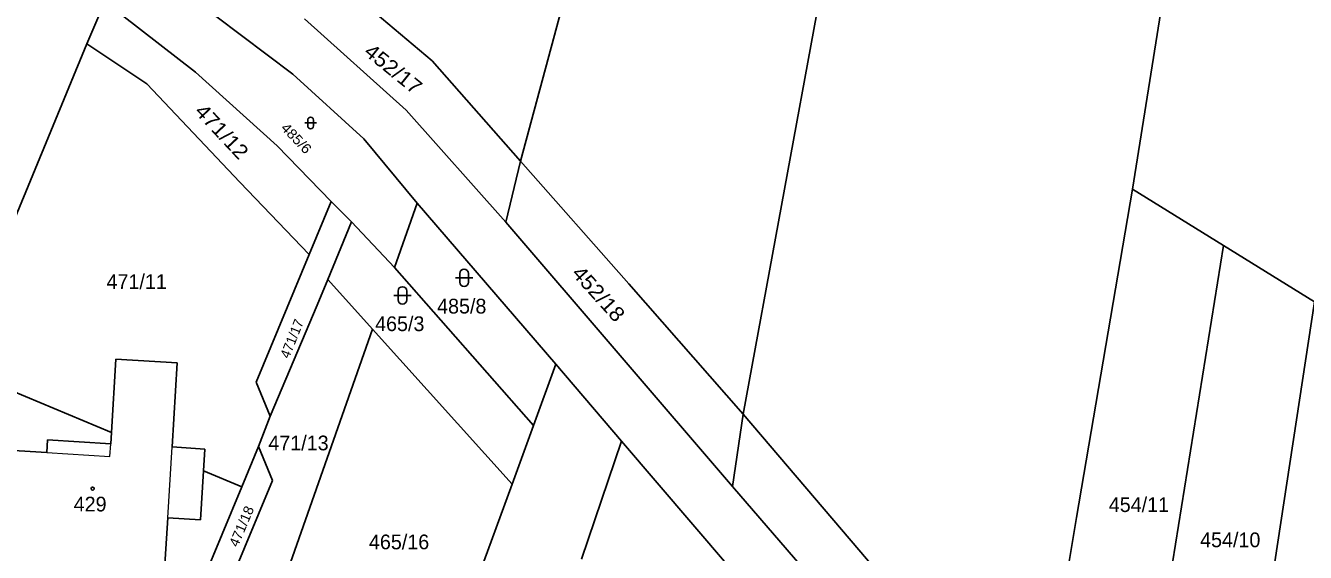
# Model space of a CAD drawing. Extents: x -701211 to -698780, y -1014269 to -1012378.
# Drawn here: x -699900.8 to -699753.2, y -1013426.5 to -1013365.7 of the extents above; entities that cross this region are included whole.
import ezdxf
from ezdxf.enums import TextEntityAlignment as Align

# ---------------------------------------------------------------- set-up
doc = ezdxf.new("R2010")
doc.units = 0
doc.header["$LTSCALE"] = 0.68
for name, color, linetype, lineweight in [('1', 7, 'Continuous', 25), ('3', 7, 'Continuous', 25), ('4', 7, 'Continuous', 13), ('5', 7, 'Continuous', 25)]:
    doc.layers.add(name, color=color, linetype=linetype, lineweight=lineweight)
doc.layers.add('2', color=7, linetype='Continuous')

msp = doc.modelspace()

# ---------------------------------------------------------------- linework, layer by layer
at = {"layer": '1'}
for p, q in [((-699773.11, -1013384.59), (-699763.06, -1013321.76)), ((-699829.74, -1013329.68), (-699843.69, -1013381.39)), ((-699806.32, -1013346.89), (-699818.01, -1013410.55)), ((-699869.94, -1013371.34), (-699889.02, -1013356.93)), ((-699853.88, -1013369.8), (-699867, -1013358.7)), ((-699893.69, -1013367.83), (-699891.63, -1013363.02)), ((-699891.63, -1013363.02), (-699881.16, -1013371.11)), ((-699856.87, -1013375.49), (-699868.6, -1013364.96)), ((-699909.05, -1013405.04), (-699893.69, -1013367.83)), ((-699893.69, -1013367.83), (-699886.78, -1013372.45)), ((-699843.69, -1013381.39), (-699853.88, -1013369.8)), ((-699881.16, -1013371.11), (-699871.73, -1013379.61)), ((-699861.76, -1013378.81), (-699869.94, -1013371.34)), ((-699886.78, -1013372.45), (-699876.06, -1013383.81)), ((-699845.37, -1013388.4), (-699856.87, -1013375.49)), ((-699871.73, -1013379.61), (-699865.53, -1013386.04)), ((-699855.6, -1013386.22), (-699861.76, -1013378.81)), ((-699845.37, -1013388.4), (-699843.69, -1013381.39)), ((-699831.2, -1013395.51), (-699843.69, -1013381.39)), ((-699876.06, -1013383.81), (-699868.05, -1013392.12)), ((-699779.57, -1013422.45), (-699773.11, -1013384.59)), ((-699773.11, -1013384.59), (-699762.6, -1013391.1)), ((-699865.53, -1013386.04), (-699868.05, -1013392.12)), ((-699863.17, -1013388.35), (-699865.53, -1013386.04)), ((-699858.22, -1013393.64), (-699855.6, -1013386.22)), ((-699839.59, -1013404.78), (-699855.6, -1013386.22)), ((-699865.9, -1013395.01), (-699863.17, -1013388.35)), ((-699858.22, -1013393.64), (-699863.17, -1013388.35)), ((-699819.25, -1013418.87), (-699845.37, -1013388.4)), ((-699762.6, -1013391.1), (-699773.55, -1013458.92)), ((-699762.6, -1013391.1), (-699752.13, -1013397.59)), ((-699868.05, -1013392.12), (-699874.17, -1013406.85)), ((-699842.18, -1013411.86), (-699858.22, -1013393.64)), ((-699867.13, -1013397.98), (-699865.9, -1013395.01)), ((-699860.73, -1013400.75), (-699865.9, -1013395.01)), ((-699818.01, -1013410.55), (-699831.2, -1013395.51)), ((-699867.13, -1013397.98), (-699872.55, -1013410.78)), ((-699762.78, -1013467.71), (-699752.13, -1013397.59)), ((-699872.65, -1013434.53), (-699860.73, -1013400.75)), ((-699844.65, -1013418.6), (-699860.73, -1013400.75)), ((-699890.85, -1013412.64), (-699890.33, -1013404.18)), ((-699890.33, -1013404.18), (-699883.26, -1013404.62)), ((-699883.26, -1013404.62), (-699883.86, -1013414.31)), ((-699839.59, -1013404.78), (-699842.18, -1013411.86)), ((-699832.02, -1013413.64), (-699839.59, -1013404.78)), ((-699909.05, -1013405.04), (-699890.85, -1013412.64)), ((-699874.17, -1013406.85), (-699872.55, -1013410.78)), ((-699819.25, -1013418.87), (-699818.01, -1013410.55)), ((-699784.21, -1013450.14), (-699818.01, -1013410.55)), ((-699873.9, -1013414.28), (-699872.55, -1013410.78)), ((-699844.65, -1013418.6), (-699842.18, -1013411.86)), ((-699898.23, -1013413.5), (-699898.32, -1013414.97)), ((-699890.93, -1013413.95), (-699898.23, -1013413.5)), ((-699890.93, -1013413.95), (-699890.85, -1013412.64)), ((-699836.63, -1013427.25), (-699832.02, -1013413.64)), ((-699819.69, -1013428.07), (-699832.02, -1013413.64)), ((-699902.78, -1013414.7), (-699898.32, -1013414.97)), ((-699880.1, -1013414.56), (-699883.86, -1013414.31)), ((-699880.25, -1013417.06), (-699880.1, -1013414.56)), ((-699873.9, -1013414.28), (-699875.82, -1013418.9)), ((-699873.9, -1013414.28), (-699872.28, -1013418.2)), ((-699880.6, -1013422.73), (-699880.25, -1013417.06)), ((-699880.25, -1013417.06), (-699875.82, -1013418.9)), ((-699875.82, -1013418.9), (-699880.91, -1013431.11)), ((-699872.28, -1013418.2), (-699878.13, -1013432.26)), ((-699844.65, -1013418.6), (-699853.39, -1013442.52)), ((-699785.49, -1013457.79), (-699819.25, -1013418.87)), ((-699884.36, -1013422.49), (-699884.73, -1013428.43)), ((-699884.36, -1013422.49), (-699880.6, -1013422.73)), ((-699784.21, -1013450.14), (-699779.57, -1013422.45))]:
    msp.add_line(p, q, dxfattribs=at)
at = {"layer": '3'}
for p, q in [((-699868.215, -1013376.635), (-699868.215, -1013377.306)), ((-699867.545, -1013377.306), (-699867.545, -1013376.635)), ((-699868.551, -1013376.971), (-699867.209, -1013376.971)), ((-699850.691, -1013394.311), (-699850.691, -1013395.312)), ((-699849.689, -1013395.312), (-699849.689, -1013394.311)), ((-699851.191, -1013394.811), (-699849.189, -1013394.811)), ((-699858.301, -1013396.841), (-699856.299, -1013396.841)), ((-699857.801, -1013396.341), (-699857.801, -1013397.342)), ((-699856.799, -1013397.342), (-699856.799, -1013396.341))]:
    msp.add_line(p, q, dxfattribs=at)
for centre, radius, start, end in [((-699867.88, -1013376.6356), 0.335, 0, 180), ((-699867.88, -1013377.3056), 0.335, 180, 359.98789), ((-699850.19, -1013394.3109), 0.5, 0, 180), ((-699857.3, -1013396.3409), 0.5, 0, 180), ((-699850.19, -1013395.3109), 0.5, 180, 359.98789), ((-699857.3, -1013397.3409), 0.5, 180, 359.98789)]:
    msp.add_arc(centre, radius, start, end, dxfattribs=at)
at = {"layer": '4'}
for p, q in [((-699898.32, -1013414.97), (-699891.02, -1013415.42)), ((-699891.02, -1013415.42), (-699890.93, -1013413.95)), ((-699884.36, -1013422.49), (-699883.86, -1013414.31))]:
    msp.add_line(p, q, dxfattribs=at)
at = {"layer": '5'}
msp.add_circle((-699893.0268, -1013419.1192), 0.175, dxfattribs=at)

# ---------------------------------------------------------------- texts
at = {"layer": '2'}
for s, height, rotation, width, p in [('452/17', 1.7, 321, 1.1, (-699858.8849, -1013371.3999)), ('485/6', 1.14, 314, 1.1, (-699869.9403, -1013379.1285)), ('452/18', 1.7, 312, 1.1, (-699835.3051, -1013397.2232)), ('471/18', 1.14, 67, 1.05, (-699875.3285, -1013423.6877))]:
    msp.add_text(s, height=height, rotation=rotation, dxfattribs=dict(at, width=width)).set_placement(p, align=Align.CENTER)
at = {"layer": '2', "width": 1.1}
msp.add_text('471/12', height=1.7, rotation=313, dxfattribs=at).set_placement((-699881.35, -1013375.729))
at = {"layer": '2'}
for s, p in [('471/11', (-699891.42, -1013396.105)), ('485/8', (-699853.3, -1013398.935)), ('465/3', (-699860.45, -1013400.965)), ('471/13', (-699872.76, -1013414.705)), ('429', (-699895.21, -1013421.755)), ('454/11', (-699775.84, -1013421.815)), ('465/16', (-699861.16, -1013426.115)), ('454/10', (-699765.31, -1013425.875))]:
    msp.add_text(s, height=1.7, dxfattribs=at).set_placement(p)
msp.add_text('471/17', height=1.14, rotation=68, dxfattribs=at).set_placement((-699869.5113, -1013402.048), align=Align.CENTER)

doc.saveas('drawing.dxf')
